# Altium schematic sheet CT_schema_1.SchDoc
size 510 x 487 mm
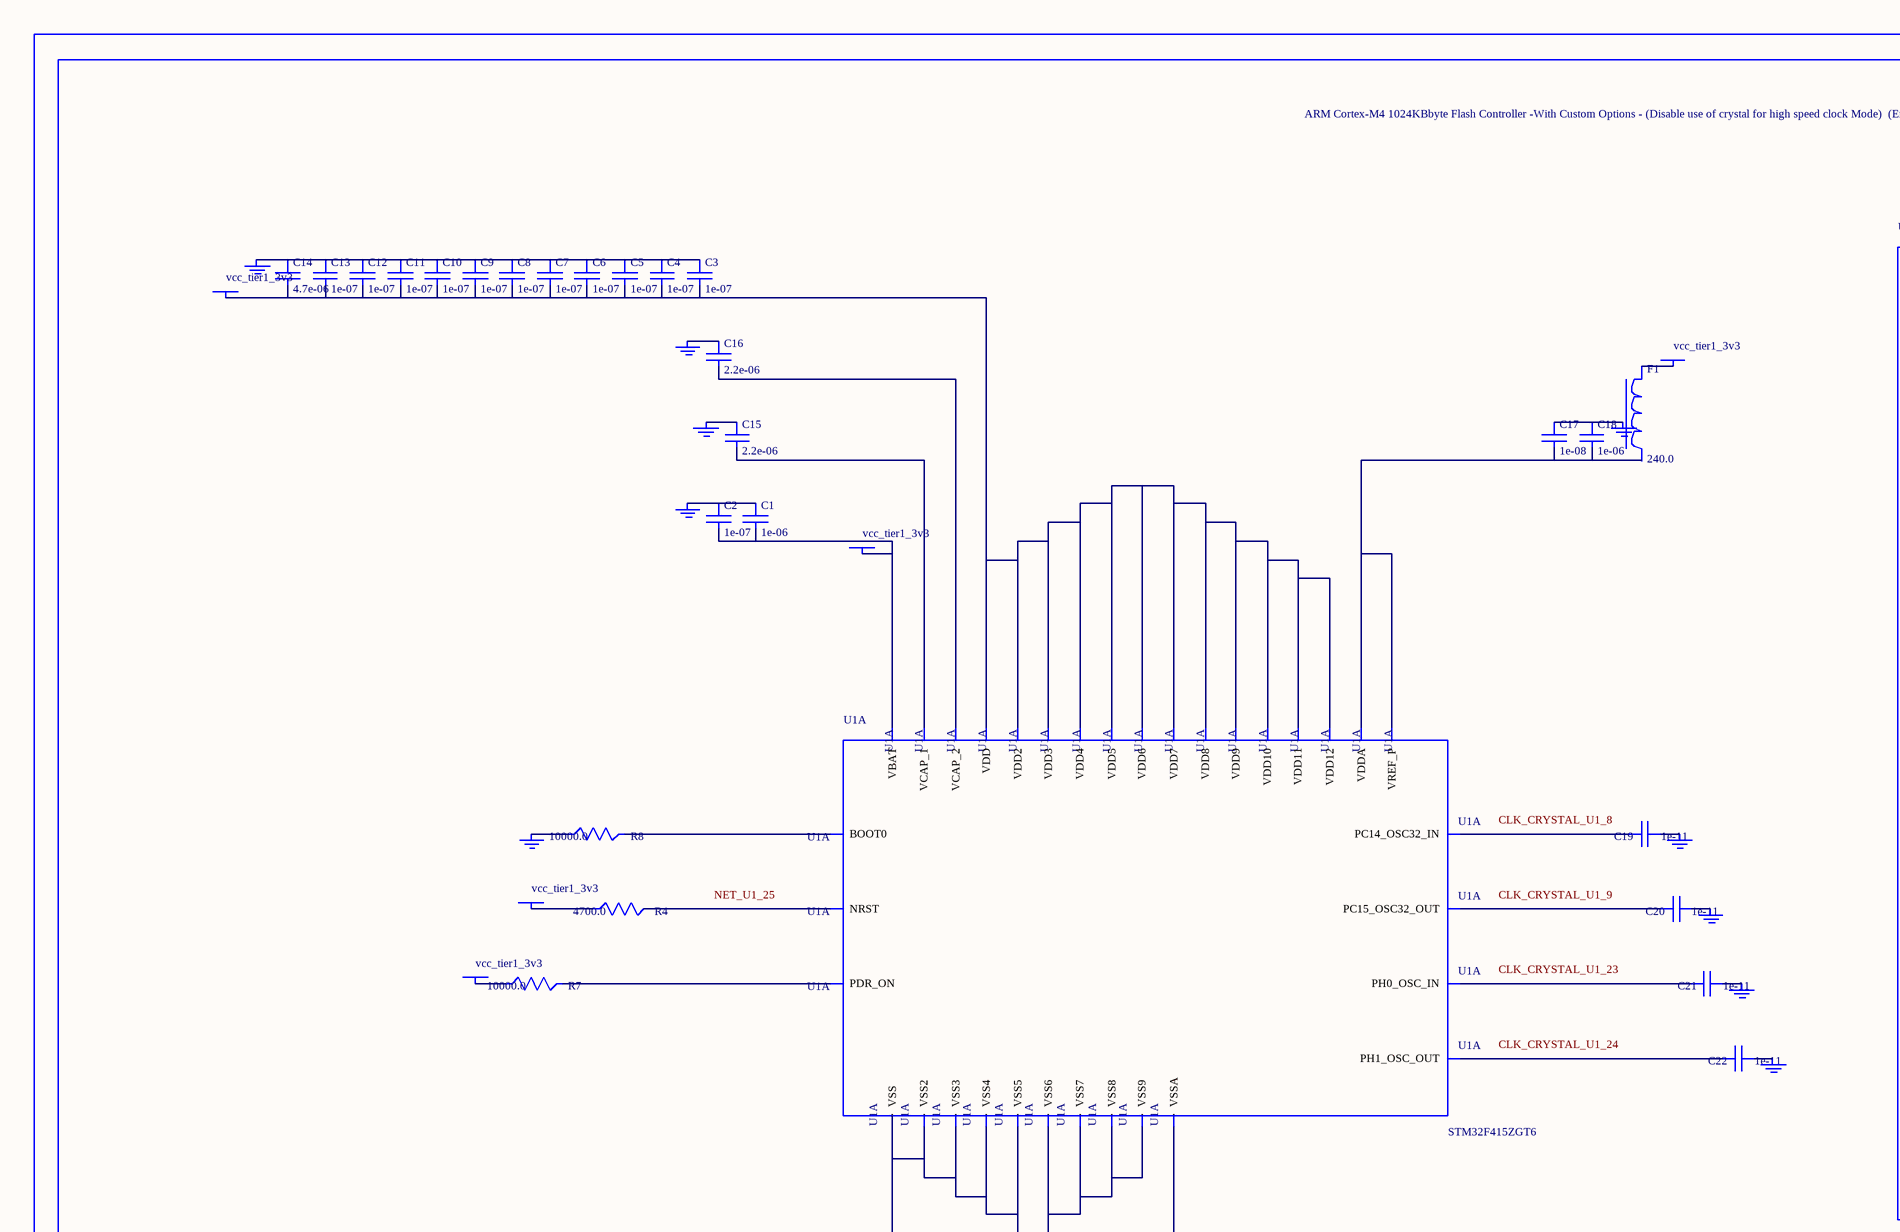
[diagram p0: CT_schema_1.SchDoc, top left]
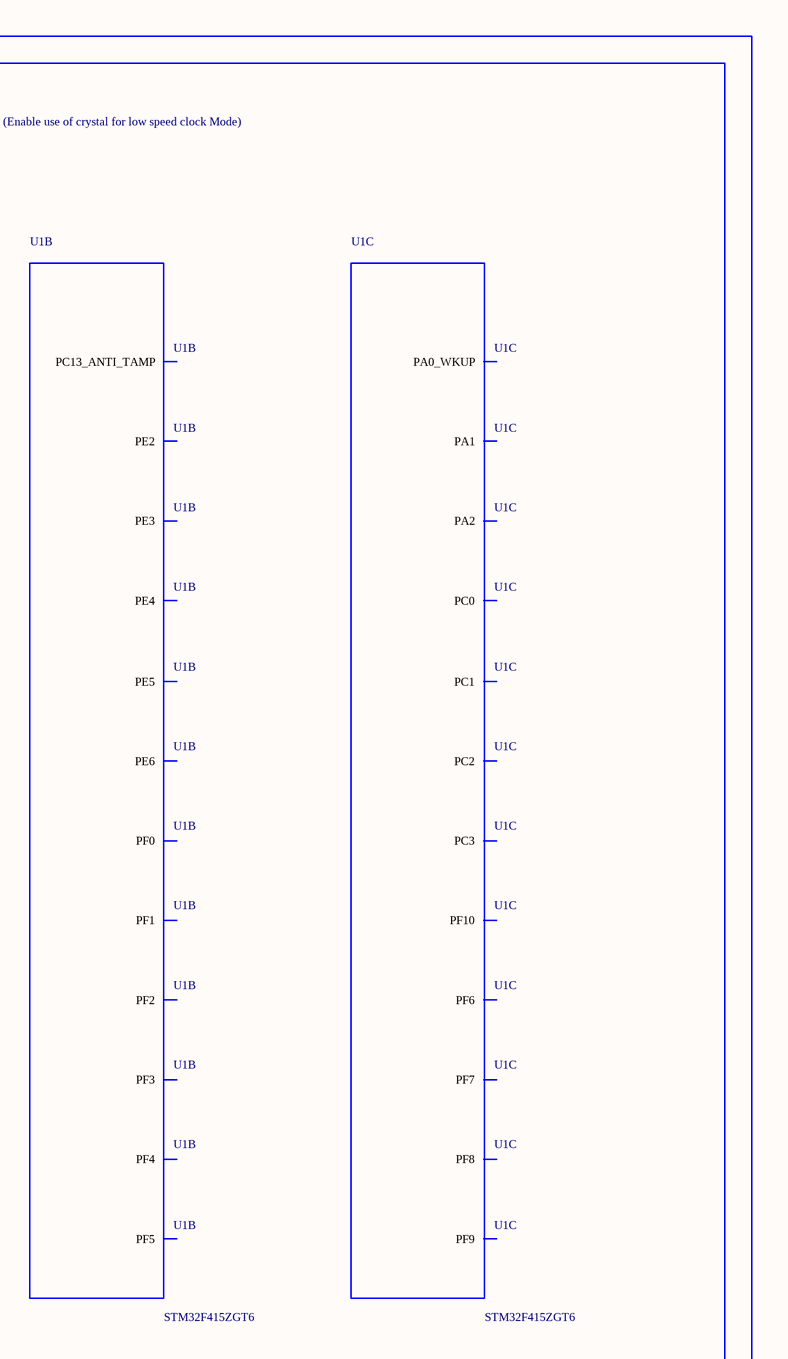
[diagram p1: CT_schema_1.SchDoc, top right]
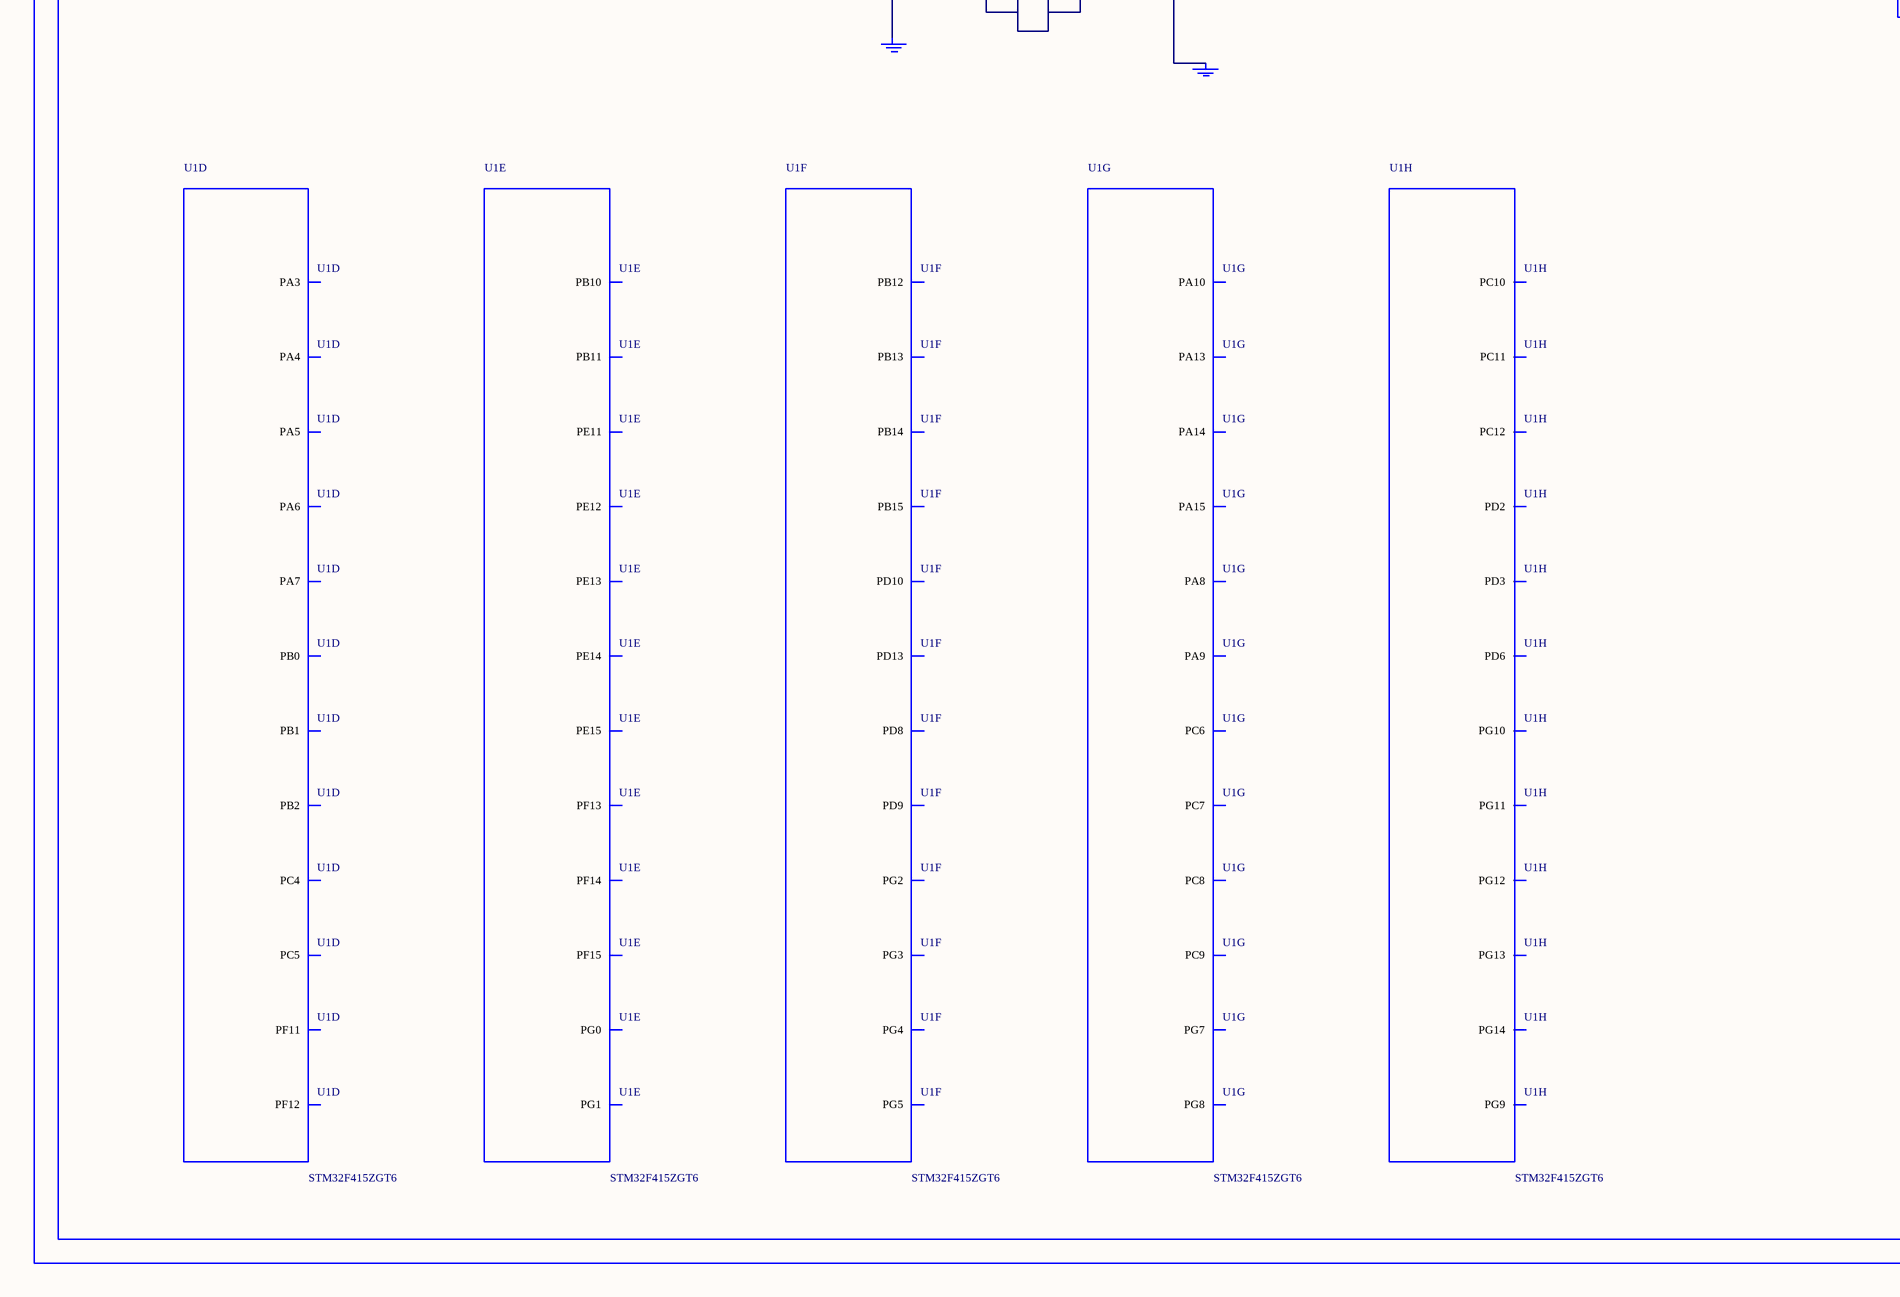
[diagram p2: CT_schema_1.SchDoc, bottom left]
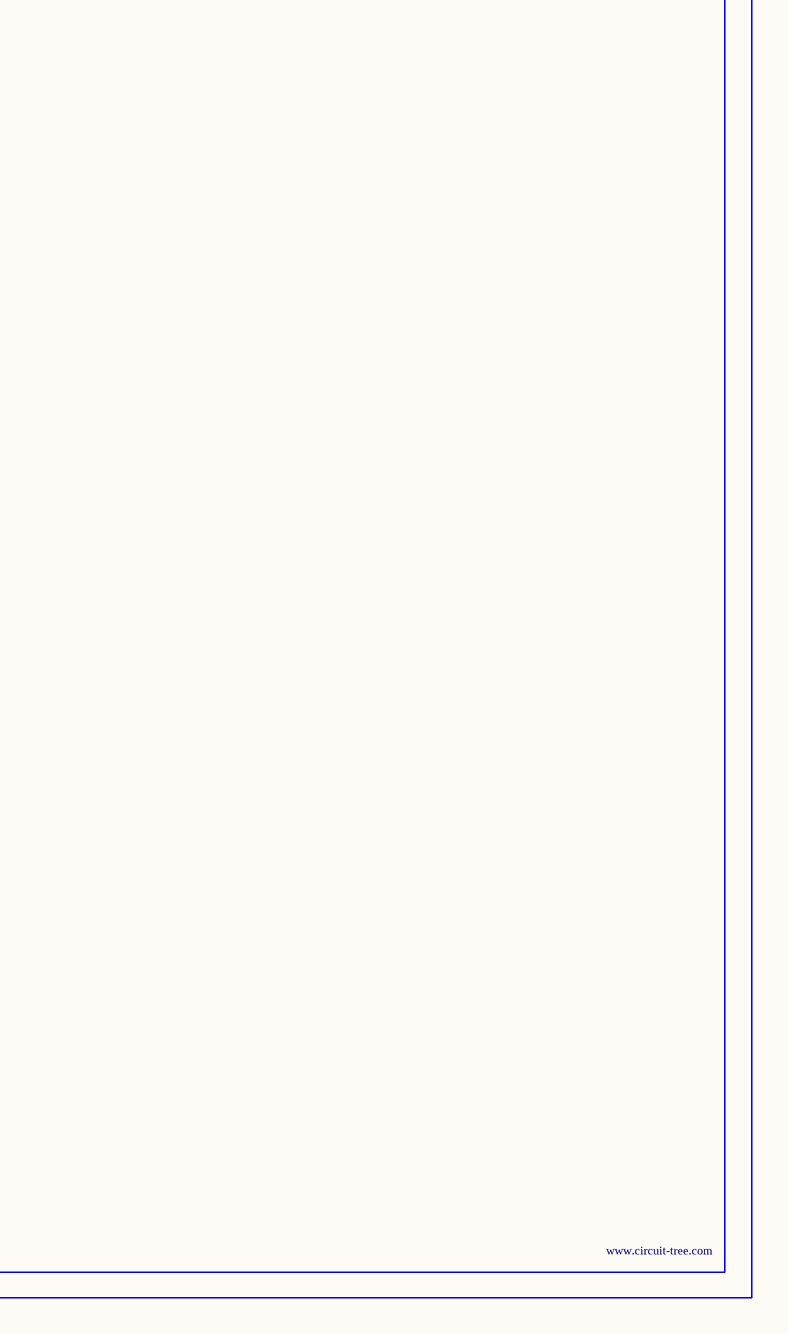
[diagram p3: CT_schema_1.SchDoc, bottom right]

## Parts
BORDER0  (no value)
C1  1e-06  [C0603]
C2  1e-07  [C0603]
C3  1e-07  [C0603]
C4  1e-07  [C0603]
C5  1e-07  [C0603]
C6  1e-07  [C0603]
C7  1e-07  [C0603]
C8  1e-07  [C0603]
C9  1e-07  [C0603]
C10  1e-07  [C0603]
C11  1e-07  [C0603]
C12  1e-07  [C0603]
C13  1e-07  [C0603]
C14  4.7e-06  [C0603]
C15  2.2e-06  [C0603]
C16  2.2e-06  [C0603]
C17  1e-08  [C0603]
C18  1e-06  [C0603]
C19  1e-11  [C0402]
C20  1e-11  [C0402]
C21  1e-11  [C0402]
C22  1e-11  [C0402]
F1  240.0  [L0603]
GND_INSTANCE_0_0  (no value)
GND_INSTANCE_0_1  (no value)
GND_INSTANCE_0_2  (no value)
GND_INSTANCE_0_3  (no value)
GND_INSTANCE_0_4  (no value)
GND_INSTANCE_0_5  (no value)
GND_INSTANCE_0_6  (no value)
GND_INSTANCE_0_7  (no value)
GND_INSTANCE_0_8  (no value)
GND_INSTANCE_0_9  (no value)
GND_INSTANCE_0_10  (no value)
GND_INSTANCE_0_11  (no value)
POWER_INSTANCE_0_0  vcc_tier1_3v3
POWER_INSTANCE_0_1  vcc_tier1_3v3
POWER_INSTANCE_0_2  vcc_tier1_3v3
POWER_INSTANCE_0_3  vcc_tier1_3v3
POWER_INSTANCE_0_4  vcc_tier1_3v3
R4  4700.0  [R0603]
R7  10000.0  [R0603]
R8  10000.0  [R0603]
U1  STM32F415ZGT6  [LQFP144]  (parts A,B,C,D,E,F,G,H of 12)

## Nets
NetC1_1: C1.1 C2.1 GND_INSTANCE_0_0.0(GND)
NetC1_2: C1.2 C2.2 POWER_INSTANCE_0_0.0(PWR) U1.6(VBAT)
NetC3_1: C3.1 C4.1 C5.1 C6.1 C7.1 C8.1 C9.1 C10.1 C11.1 C12.1 C13.1 C14.1 GND_INSTANCE_0_3.0(GND)
NetC3_2: C3.2 C4.2 C5.2 C6.2 C7.2 C8.2 C9.2 C10.2 C11.2 C12.2 C13.2 C14.2 POWER_INSTANCE_0_1.0(PWR) U1.17(VDD) U1.30(VDD2) U1.39(VDD3) U1.52(VDD4) U1.62(VDD5) U1.72(VDD6) U1.84(VDD7) U1.95(VDD8) U1.108(VDD9) U1.121(VDD10) U1.131(VDD11) U1.144(VDD12)
NetC15_1: C15.1 GND_INSTANCE_0_8.0(GND)
NetC15_2: C15.2 U1.71(VCAP_1)
NetC16_1: C16.1 GND_INSTANCE_0_9.0(GND)
NetC16_2: C16.2 U1.106(VCAP_2)
NetC17_1: C17.1 C18.1 GND_INSTANCE_0_7.0(GND)
NetC17_2: C17.2 C18.2 U1.32(VREF_P) U1.33(VDDA)
NetC19_1: C19.1 GND_INSTANCE_0_1.0(GND)
NetC19_2: C19.2 U1.8(PC14_OSC32_IN)
NetC20_1: C20.1 GND_INSTANCE_0_2.0(GND)
NetC20_2: C20.2 U1.9(PC15_OSC32_OUT)
NetC21_1: C21.1 GND_INSTANCE_0_4.0(GND)
NetC21_2: C21.2 U1.23(PH0_OSC_IN)
NetC22_1: C22.1 GND_INSTANCE_0_5.0(GND)
NetC22_2: C22.2 U1.24(PH1_OSC_OUT)
NetF1_1: F1.1 POWER_INSTANCE_0_2.0(PWR)
NetGND_INSTANCE_0_6_0: GND_INSTANCE_0_6.0(GND) U1.31(VSSA)
NetGND_INSTANCE_0_10_0: GND_INSTANCE_0_10.0(GND) R8.1
NetGND_INSTANCE_0_11_0: GND_INSTANCE_0_11.0(GND) U1.16(VSS) U1.38(VSS2) U1.51(VSS3) U1.61(VSS4) U1.83(VSS5) U1.94(VSS6) U1.107(VSS7) U1.120(VSS8) U1.130(VSS9)
NetPOWER_INSTANCE_0_3_0: POWER_INSTANCE_0_3.0(PWR) R7.1
NetPOWER_INSTANCE_0_4_0: POWER_INSTANCE_0_4.0(PWR) R4.1
NetR4_2: R4.2 U1.25(NRST)
NetR7_2: R7.2 U1.143(PDR_ON)
NetR8_2: R8.2 U1.138(BOOT0)

Not connected (* = marked no-connect by the designer): F1 2; U1 1(PE2) 2(PE3) 3(PE4) 4(PE5) 5(PE6) 7(PC13_ANTI_TAMP) 10(PF0) 11(PF1) 12(PF2) 13(PF3) 14(PF4) 15(PF5) 18(PF6) 19(PF7) 20(PF8) 21(PF9) 22(PF10) 26(PC0) 27(PC1) 28(PC2) 29(PC3) 34(PA0_WKUP) 35(PA1) 36(PA2) 37(PA3) 40(PA4) 41(PA5) 42(PA6) 43(PA7) 44(PC4) 45(PC5) 46(PB0) 47(PB1) 48(PB2) 49(PF11) 50(PF12) 53(PF13) 54(PF14) 55(PF15) 56(PG0) 57(PG1) 64(PE11) 65(PE12) 66(PE13) 67(PE14) 68(PE15) 69(PB10) 70(PB11) 73(PB12) 74(PB13) 75(PB14) 76(PB15) 77(PD8) 78(PD9) 79(PD10) 82(PD13) 87(PG2) 88(PG3) 89(PG4) 90(PG5) 92(PG7) 93(PG8) 96(PC6) 97(PC7) 98(PC8) 99(PC9) 100(PA8) 101(PA9) 102(PA10) 105(PA13) 109(PA14) 110(PA15) 111(PC10) 112(PC11) 113(PC12) 116(PD2) 117(PD3) 122(PD6) 124(PG9) 125(PG10) 126(PG11) 127(PG12) 128(PG13) 129(PG14)

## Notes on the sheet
- Labels drawn without touching a wire or pin: CLK_CRYSTAL_U1_8, CLK_CRYSTAL_U1_9, CLK_CRYSTAL_U1_23, CLK_CRYSTAL_U1_24, NET_U1_25

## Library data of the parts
BORDER0 = BORDER_PAGE0
C1 C18 = C0603C105K3RACTU
C2-C13 = 06035C104K4Z2A
C14 = GRM188R6YA475KE15D
C15 C16 = C0603C225K8RACTU
C17 = 06035C103K4Z2A
C19-C22 = C0402C100K3GACTU
F1 = Z0603C241ASMST
GND_INSTANCE_0_0-GND_INSTANCE_0_11 = GND
POWER_INSTANCE_0_0-POWER_INSTANCE_0_4 = PWR
R4 = RC0603JR-074K7L
R7 R8 = RC0603JR-0710KL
